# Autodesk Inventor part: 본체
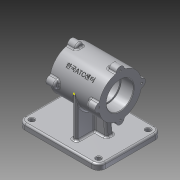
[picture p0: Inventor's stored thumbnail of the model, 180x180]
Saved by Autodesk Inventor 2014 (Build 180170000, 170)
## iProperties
Created: 2015-12
Part Number: 본체
Material: Aluminum 6061
Document SubType Name: Modeling
Designer: user
Density: 2.71 g/cm^3
Appearance: Aluminum - Flat
Mass: 1167.25 g
Surface Area: 816.133 cm^2
Volume: 430.719 cm^3
Author: user
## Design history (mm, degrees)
sketch "Sketch1"
  geometry: L1 (-42.5, 37)-(42.5, 37); L2 (42.5, 37)-(42.5, 0); L3 (42.5, 0)-(-42.5, 0); L4 (-42.5, 0)-(-42.5, 37); 2 further points
  constraints: 8 end point, 2 parallel, 1 coincident, 1 horizontal, 1 midpoint, 1 perpendicular
  dimensions: "d0" = 74 diameter of L1 L3; "d1" = 85 distance between parallel lines of L2 L4
revolve "Revolution1" sketch "Sketch1" stored, may be unused: angle "d2" = 90 deg
sketch "Sketch2"
  geometry: L1 (0, 1.084)-(0, 37); C1 r 7 at (0, 37); 2 further points
  constraints: 2 end point, 1 centre point, 1 coincident, 1 vertical, 1 vertical alignment, 1 other
  dimensions: "d3" = 14 diameter of C1
extrude "Extrusion1" join sketch "Sketch2" distance "d4" = 15; taper "d5" = 0 deg
mirror "Mirror1"
mirror "Mirror2"
sketch "Sketch5"
  geometry: L1 (-37, -37)-(37, -37); C1 r 7 at (-37, -37); A1 r 37 centre (0, -37) between (-6.969, -0.662) and (-6.969, -73.338) reference; A2 r 37 centre (0, -37) between (6.969, -73.338) and (6.969, -0.662) reference; 1 further point
  constraints: 2 end point, 2 point on circle, 1 centre point, 1 coincident
  dimensions: "d10" = 14 diameter of C1
extrude "Extrusion2" join sketch "Sketch5" distance "d11" = 15; taper "d12" = 0 deg
mirror "Mirror3"
mirror "Mirror4"
workplane "Work Plane16"
sketch "Sketch6"
  geometry: L1 (-80, 55)-(60, 55); L2 (60, 55)-(60, -55); L3 (60, -55)-(-80, -55); L4 (-80, -55)-(-80, 55); L5 (0, 0)-(0, -58.953); 1 further point
  constraints: 10 end point, 3 parallel, 1 horizontal, 1 horizontal alignment, 1 midpoint, 1 perpendicular
  dimensions: "d16" = 140 distance between parallel lines of L2 L4; "d17" = 110 distance between parallel lines of L3 L1
extrude "Extrusion3" join sketch "Sketch6" distance "d19" = 10; taper "d20" = 0 deg
sketch "Sketch7"
  geometry: L1 (0, 0)-(0, -86.371); L2 (-25, -70)-(-19.566, -25.742); L3 (-19.566, -25.742)-(19.566, -25.742); L4 (19.566, -25.742)-(25, -70); L5 (25, -70)-(-25, -70); L6 (80, -70)-(-60, -70) reference; 1 further point
  constraints: 10 end point, 1 equal length, 1 midpoint, 1 parallel, 1 perpendicular, 1 point on line, 1 vertical, 1 vertical alignment
  dimensions: "d22" = 97 deg angle of L5 L2; "d29" = 50 distance of L4.end L2.start
extrude "Extrusion4" join sketch "Sketch7" stored distance "d23" = 12; taper "d24" = 0 deg
sketch "Sketch8"
  geometry: L1 (-4, 37)-(4, 37); L2 (4, 37)-(4, -37); L3 (4, -37)-(-4, -37); L4 (-4, -37)-(-4, 37); L5 (-80, -55)-(-80, 55) reference; 3 further points
  constraints: 8 end point, 2 midpoint, 2 parallel, 1 horizontal, 1 horizontal alignment, 1 perpendicular, 1 vertical alignment
  dimensions: "d25" = 8 distance between parallel lines of L2 L4; "d26" = 74 distance between parallel lines of L3 L1
extrude "Extrusion5" join sketch "Sketch8" stored distance "d27" = 8; taper "d28" = 0 deg
sketch "Sketch9"
  geometry: L1 (-42.5, -36.338)-(-27.5, -36.338) reference; L2 (-27.5, -36.338)-(-27.5, -36.338) reference; L3 (-27.5, -36.338)-(-42.5, -36.338) reference; L4 (-42.5, -36.338)-(-42.5, -6.969) reference; L5 (-42.5, -6.969)-(-27.5, -6.969) reference; L6 (-27.5, -6.969)-(-27.5, 6.969) reference; L7 (-27.5, 6.969)-(-42.5, 6.969) reference; L8 (-42.5, 6.969)-(-42.5, 36.338) reference; L9 (-42.5, 36.338)-(-27.5, 36.338) reference; L10 (-27.5, 36.338)-(-27.5, 36.338) reference; L11 (-27.5, 36.338)-(-42.5, 36.338) reference; L12 (-42.5, 36.338)-(-42.5, 6.969) reference; L13 (-42.5, 6.969)-(-27.5, 6.969) reference; L14 (-27.5, 6.969)-(-27.5, -6.969) reference; L15 (-27.5, -6.969)-(-42.5, -6.969) reference; L16 (-42.5, -6.969)-(-42.5, -36.338) reference; L17 (27.5, -36.338)-(42.5, -36.338) reference; L18 (42.5, -6.969)-(42.5, -36.338) reference; L19 (42.5, -6.969)-(27.5, -6.969) reference; L20 (27.5, -6.969)-(27.5, 6.969) reference; L21 (27.5, 6.969)-(42.5, 6.969) reference; L22 (42.5, 36.338)-(42.5, 6.969) reference; L23 (42.5, 36.338)-(27.5, 36.338) reference; L24 (27.5, 36.338)-(27.5, 36.338) reference; L25 (27.5, 36.338)-(42.5, 36.338) reference; L26 (42.5, 6.969)-(42.5, 36.338) reference; L27 (42.5, 6.969)-(27.5, 6.969) reference; L28 (27.5, 6.969)-(27.5, -6.969) reference; L29 (27.5, -6.969)-(42.5, -6.969) reference; L30 (42.5, -36.338)-(42.5, -6.969) reference; L31 (42.5, -36.338)-(27.5, -36.338) reference; L32 (27.5, -36.338)-(27.5, -36.338) reference; L33 (-4, 0)-(4, 0) reference; L34 (-4, 0)-(-4, -36.51) reference; L35 (-4, -36.51)-(-20.888, -36.51) reference; L36 (-20.888, -36.51)-(-20.888, -36.51) reference; L37 (-20.888, -36.51)-(-4, -36.51) reference; L38 (-4, -36.51)-(-4, 0) reference; L39 (-4, 0)-(4, 0) reference; L40 (4, 0)-(4, -36.51) reference; L41 (4, -36.51)-(20.888, -36.51) reference; L42 (20.888, -36.51)-(20.888, -36.51) reference; L43 (20.888, -36.51)-(4, -36.51) reference; L44 (4, -36.51)-(4, 0) reference; L45 (-42.5, 23.5)-(-20.5, 23.5); L46 (-20.5, 23.5)-(-20.5, 21); L47 (-20.5, 21)-(20.5, 21); L48 (20.5, 21)-(20.5, 23.5); L49 (20.5, 23.5)-(42.5, 23.5); L50 (42.5, 0)-(-42.5, 0); L51 (-42.5, 23.5)-(-42.5, 0); L52 (42.5, 0)-(42.5, 23.5); 1 further point
  constraints: 16 end point, 3 collinear, 3 parallel, 3 point on line, 2 perpendicular
  dimensions: "d30" = 47 diameter of L45 L50; "d31" = 42 diameter of L47 L50; "d32" = 47 diameter of L49 L50; "d33" = 22 distance between parallel lines of L8 L46; "d34" = 41 distance between parallel lines of L48 L46
revolve "Revolution2" sketch "Sketch9" stored, may be unused: angle "d35" = 90 deg
sketch "Sketch10"
  geometry: A1 r 37 centre (0, -37) between (0, 0) and (-37, -37); 3 further points
  constraints: 4 point on circle, 1 centre point, 1 coincident
  dimensions: "d36" = 74 diameter of A1
hole "Hole1" sketch "Sketch10" at (0, 0), (-37, -37), (37, -37), (0, -74) diameter "d37" = 3.242; stored, may be unused: countersink angle "d41" = 90 deg, drill point angle "d43" = 120 deg; dims "d38" = 9, "d39" = 4, "d40" = 2, "d42" = 11
mirror "Mirror5"
sketch "Sketch11"
  geometry: L1 (-80, 55)-(60, 55) reference; L2 (60, 55)-(60, -55) reference; L3 (60, -55)-(-80, -55) reference; L4 (-80, -55)-(-80, 55) reference; L5 (48, 43)-(-68, 43); L6 (-68, 43)-(-68, -43); L7 (-68, -43)-(48, -43); L8 (48, -43)-(48, 43); C1 r 4 at (-68, 43); C2 r 4 at (-68, -43); C3 r 4 at (48, -43); C4 r 4 at (48, 43); 5 further points
  constraints: 8 coincident, 8 end point, 4 centre point, 3 equal radius, 3 other
  dimensions: "d45" = 12 distance between parallel lines of L6 L4; "d46" = 8 diameter of C1
  node "Projected Loop3"
sketch "Sketch12"
  geometry: 1 further point
extrude "Extrusion6" cut sketch "Sketch11" stored distance "d47" = 8; taper "d48" = 0 deg
fillet "Fillet1" dims "d49" = 12
fillet "Fillet2" dims "d50" = 3
fillet "Fillet3" dims "d51" = 3
fillet "Fillet4" dims "d52" = 3
fillet "Fillet5" dims "d53" = 3
fillet "Fillet6" dims "d54" = 3
chamfer "Chamfer1" distance "d55" = 1; stored, may be unused: second distance "d56" = 2, angle "d57" = 45 deg
fillet "Fillet7" dims "d58" = 0.3
fillet "Fillet8" dims "d59" = 3
sketch "Sketch14"
  geometry: 1 further point
workplane "Work Plane17"
sketch "Sketch15"
  geometry: 1 further point
sketch "Sketch16"
  geometry: 1 further point
sketch "Sketch17"
  geometry: 1 further point
sketch "Sketch18"
  geometry: L1 (0, 0)-(-27.551, 27.551); L2 (-0.03, 0.03)-(-29.041, 0.03); A1 r 37 centre (0, 0) between (-9.104, 35.863) and (-35.863, 9.104) reference; 2 further points
  constraints: 4 end point, 1 coincident, 1 horizontal, 1 point on circle, 1 point on line
  dimensions: "d61" = 45 deg angle of L2 L1
workplane "Work Plane18"
sketch "Sketch19"
  geometry: 2 further points
  constraints: 1 coincident, 1 other
emboss "Emboss1" sketch "Sketch19" dims "d62" = 0.5, "d63" = 0
chamfer "Chamfer2" distance "d64" = 1; stored, may be unused: second distance "d65" = 2, angle "d66" = 45 deg
body "Solid1"
workplane "Work Plane1"
workplane "Work Plane2"
workplane "Work Plane3"
node "Projected Loop2"
